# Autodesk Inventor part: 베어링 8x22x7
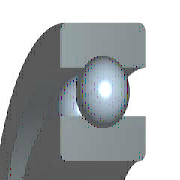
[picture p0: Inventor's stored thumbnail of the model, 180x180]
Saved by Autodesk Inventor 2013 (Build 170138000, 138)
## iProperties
IsCustomPart: 1
Created: 2012-02
Part Number: 베어링 8x22x7
Material: 강철, 연강
Description: 깊은 그루브 볼 베어링
Document SubType Name: Modeling
Standard: KS B 2023
Designer: mduedu
Standards Organization: KS
Language: ko-KR
Size Designation: 608 - 8 x 22 x 7
Categories: <MemberInstance><Categories><Category DisplayName="샤프트 부품" InternalName="7f7aeb1f-a693-4053-b835-cee3144e0d98" Mnemonic="SHFT"><Category DisplayName="베어링" Inter
Density: 7.86 g/cm^3
Mass: 12.1605 g
Surface Area: 20.0754 cm^2
Volume: 1.54714 cm^3
Author: mduedu
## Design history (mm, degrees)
sketch "스케치" dims "d0" = 3.64 (= -0.26 x WD + 0.26 x BD)
  geometry: L1 (1.68, 7.5)-(5.32, 7.5); L2 (3.5, 7.5)-(3.5, 5.68); L3 (3.5, 7.5)-(3.5, 9.32); L4 (2.148, 6.282)-(0, 6.282); L5 (0, 4)-(7, 4); L6 (2.148, 8.718)-(0, 8.718); L7 (0, 11)-(7, 11); L8 (7, 4)-(7, 6.282); L9 (4.852, 6.282)-(7, 6.282); L10 (4.852, 8.718)-(7, 8.718); L11 (7, 11)-(7, 8.718); L12 (-1.4, 0)-(8.4, 0) reference; L13 (0, -0.3)-(0, 5.3) reference
  constraints: 22 end point, 4 point on line, 2 collinear, 2 perpendicular, 2 symmetric about line, 1 midpoint, 1 parallel, 14 other
  dimensions: "d9" = 8 diameter of L5 L12 (= WD); "d11" = 22 diameter of L7 L12 (= BD); "d12" = 7 distance between parallel lines of L8 L13 (= KB); "d13" = 12.564 diameter of L9 L12 (= 0.326 x BD + 0.674 x WD)
revolve "본체" stored, may be unused: angle "d6" = 90 deg
revolve "볼" stored, may be unused: angle "d7" = 90 deg
pattern_circular "IDS_ARRAYBALL[SIMPL:T]" dims angle "d3" = 360 deg
body "Solid1"
fillet "모깎기1" dims "d1" = 0.3 (= KRS)
other parameters: "WD" = 8 [user parameter; used in 5 equation terms], "BD" = 22 [user parameter; used in 5 equation terms], "KB" = 7 [user parameter; used in 1 equation term], "KRS" = 0.3 [user parameter; used in 1 equation term], "d4" = 0, "d5" = 0, "d8" = 0, "d14" = 0, "d15" = 0, "BBA" = 0 [user parameter], "BC0" = 1370000 [user parameter], "BC" = 3250000 [user parameter], "BR" = 11 (= 0.5 x BD) [user parameter], "WR" = 4 (= 0.5 x WD) [user parameter]
